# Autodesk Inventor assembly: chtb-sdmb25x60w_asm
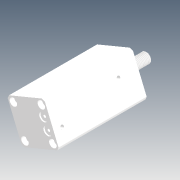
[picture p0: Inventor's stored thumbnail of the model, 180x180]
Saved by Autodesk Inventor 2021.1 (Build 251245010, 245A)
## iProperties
Company: Microsoft
Created: 2018-05
Part Number: chtb-sdmb25x60w_asm
Description: STEP AP214
Document SubType Name: Assembly
Designer: user
Title: chtb-sdmb25x60w_asm.STEP
Author: Windows
Revision Number: ÈÎºÎ
Sending System: SolidWorks 2015
Preprocessor: SwSTEP 2.0
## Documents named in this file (4)
- D:\Vault_2016\Projekty\Clamptek\Hydraulic\CHTB\CHTB-25\Inventor\chtb-sdmb25x60w\chtb-sdmb25x60w_asm.iam
- D:\Vault_2016\Projekty\Clamptek\Hydraulic\CHTB\CHTB-25\Inventor\chtb-sdmb25x60w\CHTB-25QG.ipt
- D:\Vault_2016\Projekty\Clamptek\Hydraulic\CHTB\CHTB-25\Inventor\chtb-sdmb25x60w\CHTB-SDMB25X60NBT.ipt
- D:\Vault_2016\Projekty\Clamptek\Hydraulic\CHTB\CHTB-25\Inventor\chtb-sdmb25x60w\CHTB-SDMB25X60WHSG.ipt
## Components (3 placed, 3 different names)
1. CHTB-25QG_1
2. CHTB-SDMB25X60NBT_2
3. CHTB-SDMB25X60WHSG_3
